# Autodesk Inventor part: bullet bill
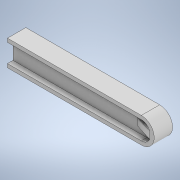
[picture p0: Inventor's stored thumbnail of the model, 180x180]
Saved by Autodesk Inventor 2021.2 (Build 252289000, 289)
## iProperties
Created: 2021-01
Part Number: bullet bill
Material: Generic
Document SubType Name: Modeling
Designer: josep
Density: 1 g/cm^3
Appearance: Default
Author: josep
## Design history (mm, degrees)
sketch "Sketch1"
  geometry: L1 (34, 12.5)-(31, 12.5); L2 (35, 12.5)-(34, 12.5); L3 (31, 12.5)-(30, 12.5); L4 (35, -12.5)-(34, -12.5); L5 (30, -12.5)-(31, -12.5); L6 (5, -12.5)-(4, -12.5); L7 (1, -12.5)-(0, -12.5); L8 (4, 12.5)-(5, 12.5); L9 (0, 12.5)-(1, 12.5); L10 (35, 5)-(0, 5); L11 (0, 5)-(0, -5); L12 (0, -5)-(35, -5); L13 (35, -5)-(35, 5); L14 (0, 12.5)-(5, 12.5); L15 (5, 12.5)-(0, 12.5); L16 (0, 12.5)-(0, 5); L17 (0, 5)-(5, 5); L18 (5, 5)-(5, 12.5); L19 (5, -12.5)-(0, -12.5); L20 (0, -12.5)-(0, -5); L21 (0, -5)-(5, -5); L22 (5, -5)-(5, -12.5); L23 (35, 12.5)-(30, 12.5); L24 (30, 12.5)-(30, 5); L25 (30, 5)-(35, 5); L26 (35, 5)-(35, 12.5); L27 (35, -12.5)-(30, -12.5); L28 (30, -12.5)-(30, -5); L29 (30, -5)-(35, -5); L30 (35, -5)-(35, -12.5); 15 further points
  constraints: 60 end point, 10 parallel, 7 horizontal, 7 point on line, 5 perpendicular
extrude "Extrusion1" new body sketch "Sketch1" distance "d19" = 82.5; taper "d20" = 0 deg; dims "d26" = 100, "d27" = 0
extrude "Extrusion2" join sketch "Sketch1" stored distance "d21" = 200; taper "d22" = 0 deg
sketch "Sketch2"
  geometry: L1 (200, 0)-(200, 35) reference; L2 (182.5, 35)-(200, 35) reference; L3 (200, 0)-(100, 0) reference; L4 (182.5, 35)-(200, 35); L5 (200, 17.5)-(200, 0); L6 (0, 30)-(182.5, 30) reference; L7 (182.5, 30)-(182.5, 35) reference; L8 (182.5, 30)-(182.5, 35); L9 (0, 5)-(182.5, 5) reference; L10 (182.5, 0)-(182.5, 5) reference; L11 (182.5, 5)-(182.5, 0); A1 r 17.5 centre (182.5, 17.5) between (182.5, 0) and (182.5, 35); A2 r 12.5 centre (182.5, 17.5) between (182.5, 5) and (182.5, 30); 2 further points
  constraints: 9 end point, 5 point on circle, 2 centre point, 2 tangent, 2 vertical, 1 coincident, 1 collinear, 1 perpendicular, 1 point on line
extrude "Extrusion3" cut sketch "Sketch2" distance "d24" = 20; taper "d25" = 0 deg
extrude "Extrusion4" join sketch "Sketch2" distance "d28" = 7.5; taper "d30" = 0 deg; dims "d29" = 17.5, "d31" = 0
sketch "Sketch3"
  geometry: L1 (195, 12.5)-(195, 17.5); L2 (195, 12.5)-(195, 7.5); L3 (195, 17.5)-(170, 17.5); L4 (170, 17.5)-(170, 7.5); L5 (170, 7.5)-(195, 7.5); A1 r 12.5 centre (182.5, 12.5) between (182.5, 0) and (182.5, 25) reference; 3 further points
  constraints: 10 end point, 2 perpendicular, 1 horizontal, 1 point on circle, 1 point on line, 1 tangent, 1 vertical
extrude "Extrusion5" join sketch "Sketch3" distance "d36" = 7.5; taper "d38" = 0 deg; dims "d37" = 17.5, "d39" = 0
sketch "Sketch4"
  geometry: L1 (23.956, -7.5)-(0, -7.5) reference; L2 (0, 0)-(23.956, -7.5); L3 (23.956, -7.5)-(0, -7.5); L4 (-170, 17.5)-(12.5, 17.5) reference; L5 (0, -7.5)-(0, 0); 2 further points
  constraints: 6 end point, 1 parallel, 1 perpendicular
extrude "Extrusion6" cut sketch "Sketch4" distance "d40" = 10; taper "d41" = 0 deg
sketch "Sketch5"
  geometry: L1 (23.956, 7.5)-(23.956, 0) reference; L2 (23.956, 7.5)-(0, 0); L3 (0, 7.5)-(0, 0) reference; L4 (0, 0)-(0, 7.5); L5 (0, 7.5)-(23.956, 7.5) reference; L6 (0, 7.5)-(23.956, 7.5); 1 further point
  constraints: 6 end point, 1 perpendicular, 1 vertical
extrude "Extrusion7" cut sketch "Sketch5" distance "d42" = 10; taper "d43" = 0 deg
body "Solid1"
